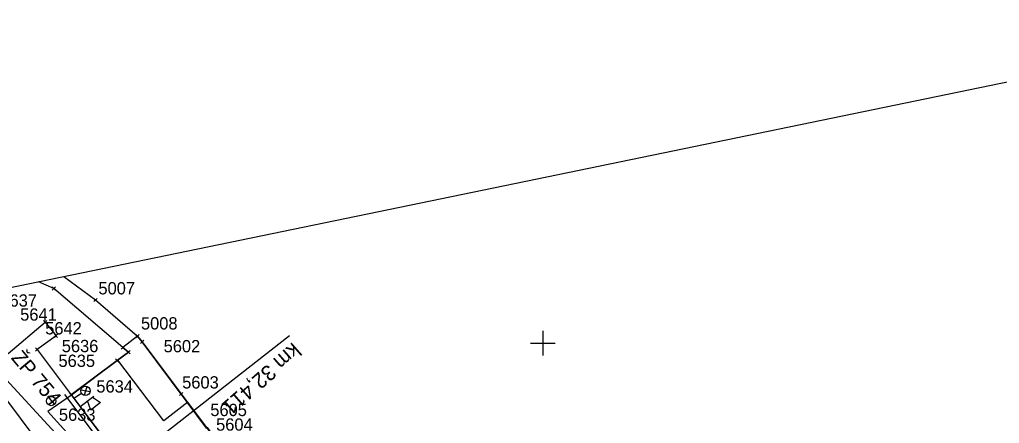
# Model space of a CAD drawing. Extents: x -804166 to -803706, y -1151030 to -1150147.
# Drawn here: x -804085.1 to -803925.7, y -1150213 to -1150147.3 of the extents above; entities that cross this region are included whole.
import ezdxf

# ---------------------------------------------------------------- set-up
doc = ezdxf.new("R2010")
doc.units = 0
for name, color, linetype in [('0381KM032-037P - Vrstva 1', 7, 'Continuous'), ('0381KM032-037P - Vrstva 16', 7, 'Continuous'), ('0381KM032-037P - Vrstva 23', 7, 'Continuous'), ('0381KM032-037P - Vrstva 25', 7, 'Continuous'), ('0381KM032-037P - Vrstva 3', 7, 'Continuous'), ('0381KM032-037P - Vrstva 33', 7, 'Continuous'), ('0381KM032-037P - Vrstva 55', 7, 'Continuous'), ('formát', 7, 'Continuous'), ('krizky_1000 - Vrstva 1', 7, 'Continuous'), ('szdc - hran DP', 7, 'Continuous'), ('szdc - szdc_cislo', 7, 'Continuous'), ('szdc - szdc_krizek', 7, 'Continuous'), ('vyt_sit - stávající', 7, 'Continuous')]:
    doc.layers.add(name, color=color, linetype=linetype)

msp = doc.modelspace()

# ---------------------------------------------------------------- linework, layer by layer
at = {"layer": '0381KM032-037P - Vrstva 1'}
for points in [[(-804087.93, -1150205.28), (-804078.71, -1150215.28), (-804072.37, -1150222.52), (-804072.08, -1150222.85), (-804071.47, -1150223.58), (-804065.48, -1150230.82), (-804059.47, -1150238.51), (-804055.55, -1150243.68), (-804054.36, -1150245.27), (-804043.89, -1150259.22), (-804035.37, -1150270.61), (-804034.4, -1150271.93), (-804017.97, -1150293.92), (-804002.6, -1150314.46), (-803985.38, -1150337.43), (-803955.87, -1150376.72)], [(-804089.35, -1150206.44), (-804078.67, -1150220.7), (-804069.15, -1150233.38), (-804067.86, -1150235.11), (-804059.28, -1150246.53), (-804058.07, -1150248.16), (-804048.7, -1150260.65), (-804037.85, -1150275.13), (-804021.63, -1150296.76), (-804006.14, -1150317.34), (-803988.98, -1150340.29), (-803981.9, -1150349.73)]]:
    msp.add_lwpolyline(points, dxfattribs=at)
at = {"layer": '0381KM032-037P - Vrstva 16'}
msp.add_lwpolyline([(-804076.66, -1150208.44), (-804080.54, -1150211.1), (-804072.9, -1150219.59), (-804065.93, -1150227.88), (-804061.29, -1150233.69), (-804055.95, -1150240.78), (-804053.73, -1150239.04)], dxfattribs=at)
at = {"layer": '0381KM032-037P - Vrstva 23'}
for p, q in [((-804069.12, -1150202.75), (-804076.66, -1150208.44)), ((-804061.66, -1150212.61), (-804069.12, -1150202.75)), ((-804076.66, -1150208.44), (-804070.85, -1150216.23)), ((-804057.75, -1150209.57), (-804061.66, -1150212.61)), ((-804046.83, -1150224.17), (-804057.75, -1150209.57))]:
    msp.add_line(p, q, dxfattribs=at)
msp.add_lwpolyline([(-804045.33, -1150233.58), (-804054, -1150239.88), (-804077.77, -1150208.37)], dxfattribs=at)
at = {"layer": '0381KM032-037P - Vrstva 25'}
for p, q in [((-804073.67, -1150207.9), (-804075.16, -1150207.64)), ((-804074.21, -1150207.04), (-804074.61, -1150208.49)), ((-804075.05, -1150208.17), (-804076.31, -1150208.99))]:
    msp.add_line(p, q, dxfattribs=at)
msp.add_circle((-804074.42, -1150207.76), 0.754, dxfattribs=at)
at = {"layer": '0381KM032-037P - Vrstva 3'}
msp.add_line((-804072.08, -1150222.85), (-804041.24, -1150198.77), dxfattribs=at)
at = {"layer": '0381KM032-037P - Vrstva 33'}
msp.add_line((-804075.25, -1150210.32), (-804073.04, -1150208.6), dxfattribs=at)
msp.add_lwpolyline([(-804073.28, -1150208.79), (-804071.96, -1150209.67), (-804073.54, -1150210.89), (-804074.07, -1150209.4)], dxfattribs=at)
at = {"layer": '0381KM032-037P - Vrstva 55'}
msp.add_lwpolyline([(-804076.76, -1150208.41), (-804070.92, -1150216.16), (-804056.87, -1150234.96), (-804053.79, -1150239.08), (-804046.26, -1150233.41), (-804050.84, -1150227.18), (-804046.86, -1150224.2), (-804050.01, -1150220.06), (-804049.93, -1150219.91), (-804054.58, -1150213.71), (-804054.7, -1150213.8), (-804057.84, -1150209.6), (-804058.02, -1150209.36), (-804065.16, -1150199.8), (-804065.96, -1150198.88), (-804068.34, -1150200.69), (-804067.42, -1150201.47), (-804069.26, -1150202.82)], close=True, dxfattribs=at)
at = {"layer": 'formát'}
msp.add_line((-804166.3, -1150207.4), (-803875.43, -1150147.35), dxfattribs=at)
at = {"layer": 'krizky_1000 - Vrstva 1'}
for points in [[(-804000, -1150198), (-804000, -1150202)], [(-804002, -1150200), (-803998, -1150200)]]:
    msp.add_lwpolyline(points, dxfattribs=at)
at = {"layer": 'szdc - hran DP'}
for p, q in [((-804079.56, -1150191.12), (-804082.03, -1150190)), ((-804068.34, -1150200.69), (-804079.56, -1150191.12)), ((-804087, -1150201.67), (-804080.94, -1150196.58)), ((-804080.94, -1150196.58), (-804079.2, -1150198.82)), ((-804079.2, -1150198.82), (-804082.27, -1150201.05)), ((-804065.96, -1150198.88), (-804065.16, -1150199.8)), ((-804065.16, -1150199.8), (-804058.84, -1150208.26)), ((-804082.27, -1150201.05), (-804076.76, -1150208.41)), ((-804069.26, -1150202.82), (-804067.42, -1150201.47)), ((-804067.42, -1150201.47), (-804068.34, -1150200.69)), ((-804076.76, -1150208.41), (-804069.26, -1150202.82)), ((-804058.84, -1150208.26), (-804054.7, -1150213.8))]:
    msp.add_line(p, q, dxfattribs=at)
msp.add_lwpolyline([(-804077.91, -1150189.15), (-804072.79, -1150192.97), (-804065.96, -1150198.88)], dxfattribs=at)
at = {"layer": 'szdc - szdc_krizek'}
for p, q in [((-804079.3, -1150191.39), (-804079.83, -1150190.85)), ((-804079.83, -1150191.39), (-804079.3, -1150190.85)), ((-804072.53, -1150193.24), (-804073.06, -1150192.71)), ((-804073.06, -1150193.24), (-804072.53, -1150192.71)), ((-804080.68, -1150196.84), (-804081.21, -1150196.31)), ((-804081.21, -1150196.84), (-804080.68, -1150196.31)), ((-804078.94, -1150199.08), (-804079.47, -1150198.55)), ((-804079.47, -1150199.08), (-804078.94, -1150198.55)), ((-804065.7, -1150199.15), (-804066.23, -1150198.61)), ((-804066.23, -1150199.15), (-804065.7, -1150198.61)), ((-804064.9, -1150200.06), (-804065.43, -1150199.53)), ((-804065.43, -1150200.06), (-804064.9, -1150199.53)), ((-804082.01, -1150201.31), (-804082.54, -1150200.78)), ((-804082.54, -1150201.31), (-804082.01, -1150200.78)), ((-804068.08, -1150200.96), (-804068.61, -1150200.43)), ((-804068.61, -1150200.96), (-804068.08, -1150200.43)), ((-804067.16, -1150201.74), (-804067.69, -1150201.21)), ((-804067.69, -1150201.74), (-804067.16, -1150201.21)), ((-804068.99, -1150203.08), (-804069.53, -1150202.55)), ((-804069.53, -1150203.08), (-804068.99, -1150202.55)), ((-804076.49, -1150208.68), (-804077.03, -1150208.15)), ((-804077.03, -1150208.68), (-804076.49, -1150208.15)), ((-804058.58, -1150208.53), (-804059.11, -1150208)), ((-804059.11, -1150208.53), (-804058.58, -1150208))]:
    msp.add_line(p, q, dxfattribs=at)
at = {"layer": 'vyt_sit - stávající'}
msp.add_line((-804080.02, -1150209.41), (-804079.92, -1150209.41), dxfattribs=at)
msp.add_circle((-804079.97, -1150209.41), 0.756, dxfattribs=at)

# ---------------------------------------------------------------- texts
at = {"layer": '0381KM032-037P - Vrstva 3'}
msp.add_text('km 32,411', height=2.5, rotation=221.1865, dxfattribs=at).set_placement((-804040.7, -1150199.75))
at = {"layer": 'szdc - szdc_cislo'}
for s, p in [('5007', (-804072.3, -1150192.06)), ('5637', (-804088.25, -1150194.05)), ('5641', (-804085.03, -1150196.33)), ('5642', (-804080.96, -1150198.57)), ('5008', (-804065.38, -1150197.77)), ('5636', (-804078.26, -1150201.46)), ('5602', (-804061.69, -1150201.48)), ('5635', (-804078.8, -1150203.86)), ('5634', (-804072.64, -1150208.03)), ('5603', (-804058.68, -1150207.37)), ('5633', (-804078.73, -1150212.63)), ('5605', (-804054.1, -1150211.86)), ('5604', (-804053.16, -1150214.23))]:
    msp.add_text(s, height=2, dxfattribs=at).set_placement(p)
at = {"layer": 'vyt_sit - stávající'}
msp.add_text('ŽP 754', height=2.4, rotation=310, dxfattribs=at).set_placement((-804086.61, -1150202.44))

doc.saveas('drawing.dxf')
